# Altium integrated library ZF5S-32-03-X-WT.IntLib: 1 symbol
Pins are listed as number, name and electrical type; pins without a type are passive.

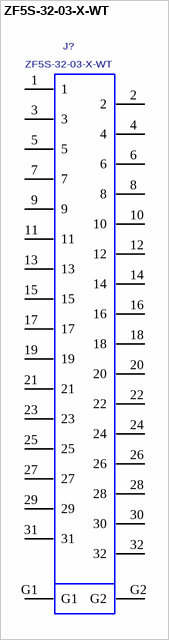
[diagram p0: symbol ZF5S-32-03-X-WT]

## ZF5S-32-03-X-WT
designator J?
ZERO INSERTION FORCE 0.5MM ASSEMBLY, 03 LEAD STYLE.; MANUFACTURER: SAMTEC
footprint ZF5S-32-03-X-WT
pins: 1, 2, 3, 4, 5, 6, 7, 8, 9, 10, 11, 12, 13, 14, 15, 16, 17, 18, 19, 20, 21, 22, 23, 24, 25, 26, 27, 28, 29, 30, 31, 32, G1, G2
